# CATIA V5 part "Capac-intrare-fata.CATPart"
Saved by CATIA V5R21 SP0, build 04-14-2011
Part number: Part1.5
Bounding box of the stored display mesh (mm): x -45.992 to 45.967, y 0 to 21.5, z -45.932 to 45.2
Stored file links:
  C:\Users\MIRCEA\Desktop\MOM\Mogan\model\Capac-intrare-fata.CATPart
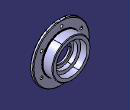
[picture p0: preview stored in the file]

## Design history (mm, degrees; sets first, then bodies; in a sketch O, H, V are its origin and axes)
Body1 (main body)
  Sketch1 on yz-plane, origin (0, 0, 0), H (0, 1, 0), V (0, 0, 1)
    line L1 (0, 0) -> (5, 0)
    line L2 (0, 0) -> (0, 46)
    point P2 (0, 46)
    line L3 (0, 46) -> (5, 46)
    point P3 (5, 46)
    line L4 (5, 46) -> (5, 31)
    line L5 (5, 31) -> (21.5, 31)
    line L6 (21.5, 31) -> (21.5, 25)
    line L7 (5, 20) -> (11.5, 20)
    line L8 (11.5, 20) -> (11.5, 25)
    line L9 (5, 20) -> (5, 0)
    line L10 (11.5, 25) -> (21.5, 25)
    length L1 = 5
    length L2 = 46
    length L4 = 15
    length L5 = 16.5
    length L6 = 6
    distance P3 P2 = 5
    length L7 = 6.5
    horizontal: L1 H, L3 H, L5 H, L7 H, L10 H
    vertical: L2 V, L4 V, L6 V, L8 V, L9 V
  Shaft1: profile Sketch1, axis Sketch1.L1, angle 360
  Sketch2 on face of Shaft1 from Sketch1.L2, origin (0, 0, 0), H (1, 0, 0), V (0, 0, 1)
    point P1 (0, 37.5)
    distance P1 O = 37.5
  Sketch3 on face of Shaft1 from Sketch1.L2, origin (0, 0, 47.5), H (1, 0, 0), V (0, 0, 1)
    point P1 (0, -10)
    reference projected point E1 (0, -10) from Sketch2.P1
    coincidence: E1 P1
  Hole1: placed by Sketch3, at (0, 0, 37.5) direction (0, 1, 0), diameter 5, through (limit type 6)
  CircPattern1: of Hole1, instances 6, angular step 60 {= 360.0*1 deg/CircPattern1.AngularNumber}, axis from face of Shaft1 from Sketch1.L2
  Sketch4 on zx-plane, origin (0, 0, 0), H (-1, 0, 0), V (0, 0, 1)
    point P1 (0, 45.2)
    line L1 (0, 45.2) -> (14.9451, 45.2)
    line L2 (0, 45.2) -> (-11.9737, 45.2)
    line L3 (-11.9737, 45.2) -> (-11.9737, 46.4989)
    line L4 (14.9451, 45.2) -> (14.9451, 46.4989)
    line L5 (14.9451, 46.4989) -> (-11.9737, 46.4989)
    distance O P1 = 45.2
    horizontal: L1 H, L2 H, L5 H
    vertical: L3 V, L4 V
  Pocket1: profile Sketch4, direction (0, 1, 0), length 20
  Sketch5 on face of Shaft1 from Sketch1.L2, origin (0, 0, 0), H (1, 0, 0), V (0, 0, 1)
    circle A1 centre (0, 0) radius 15
    radius A1 = 15
  Pocket2: profile Sketch5, direction (0, 1, 0), through (limit type 6)
  DatumCurve1
  Sketch6 on yz-plane, origin (0, 0, 0), H (0, 1, 0), V (0, 0, 1)
    point P1 (5, 31.0612)
    line L1 (5.04, 32.24) -> (4.7784, 31.2749)
    arc A1 centre (5.1121, 31.1844) radius 0.3458 from (4.7784, 31.2749) to (5.04, 30.8462) ccw
    line L2 (5.04, 30.8462) -> (5.5473, 30.7644)
    arc A2 centre (5.6735, 31.5471) radius 0.7927 from (5.5473, 30.7644) to (6.2494, 31.0022) ccw
    distance P1 V = 5
    length L1 = 1
    tangency: A1 L1, A2 L1, A2 L2
  Groove1: profile Sketch6, axis edge of DatumCurve1, angle 360
  Chamfer1: length 1, angle 45, on edge [face of Shaft1 from Sketch1.L5 | face of Shaft1 from Sketch1.L6]
  Chamfer2: length 1, angle 45, on edge [face of Shaft1 from Sketch1.L3 | face of Shaft1 from Sketch1.L4]; edge [face of Shaft1 from Sketch1.L2 | face of Shaft1 from Sketch1.L3]; edge [face of Shaft1 from Sketch1.L2 | face of Pocket2 from Sketch5.A1]; edge [face of Shaft1 from Sketch1.L9 | face of Pocket2 from Sketch5.A1]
